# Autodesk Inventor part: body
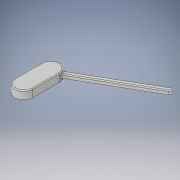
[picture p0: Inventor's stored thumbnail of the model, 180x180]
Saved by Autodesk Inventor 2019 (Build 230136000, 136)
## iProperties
Created: 2020-09
Part Number: body
Material: 一般
Document SubType Name: Modeling
Designer: kikut
Density: 1 g/cm^3
Appearance: 既定
Author: kikut
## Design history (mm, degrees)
sketch "スケッチ1"
  geometry: L1 (0.02, 0)-(-0.02, 0); L2 (-0.02, 0)-(-0.02, 0.06); L3 (-0.02, 0.06)-(0.02, 0.06); L4 (0.02, 0.06)-(0.02, 0); L5 (0.02, 0)-(-0.02, 0.06); L6 (-0.02, 0)-(0.02, 0.06); A1 r 0.02 centre (0, 0.06) between (0.02, 0.06) and (-0.02, 0.06); A2 r 0.02 centre (0, 0) between (-0.02, 0) and (0.02, 0); 2 further points
  constraints: 12 end point, 4 midpoint, 4 point on circle, 2 centre point, 2 parallel, 1 coincident, 1 horizontal, 1 perpendicular
  dimensions: "d0" = 0.04 distance of L2.end L3.end; "d1" = 0.06 distance of L3.end L1.start
extrude "押し出し1" new body sketch "スケッチ1" stored distance "d2" = 0.02; taper "d3" = 0 deg
sketch "スケッチ2"
  geometry: L1 (-0.171, -0.105)-(0.002, -0.005); L2 (0.002, -0.005)-(-0.003, 0.004); L3 (-0.003, 0.004)-(-0.176, -0.096); L4 (-0.176, -0.096)-(-0.171, -0.105); L5 (-0.171, -0.105)-(-0.003, 0.004); L6 (0.002, -0.005)-(-0.176, -0.096); L7 (0.062, 0)-(-0.232, 0) reference; 2 further points
  constraints: 12 end point, 2 midpoint, 2 parallel, 1 perpendicular
  dimensions: "d4" = 0.01 distance of L1.end L2.end; "d5" = 0.2 distance of L2.end L3.end; "d6" = 30 deg angle of L3 L7
extrude "押し出し2" join sketch "スケッチ2" stored distance "d7" = 0.01; taper "d8" = 0 deg
fillet "フィレット2" dims "d10" = 0.005
fillet "フィレット3" dims "d11" = 0.002
node "ソリッド1"
